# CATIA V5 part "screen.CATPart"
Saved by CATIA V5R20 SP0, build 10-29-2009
Part number: Part5
Bounding box of the stored display mesh (mm): x 0 to 20, y -138 to 138, z -107.5 to 107.5
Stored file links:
  C:\Users\HP\Downloads\Catia Project\Catia Project\screen.CATPart
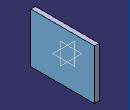
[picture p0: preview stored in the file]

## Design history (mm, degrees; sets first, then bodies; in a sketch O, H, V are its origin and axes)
Body1 (main body)
  Sketch1 on yz-plane, origin (0, 0, 0), H (0, 1, 0), V (0, 0, 1)
    line L1 (138, 107.5) -> (138, -107.5)
    line L2 (138, -107.5) -> (-138, -107.5)
    line L3 (-138, -107.5) -> (-138, 107.5)
    line L4 (-138, 107.5) -> (138, 107.5)
  Pad1: profile Sketch1, direction (1, 0, 0), length 20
